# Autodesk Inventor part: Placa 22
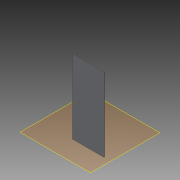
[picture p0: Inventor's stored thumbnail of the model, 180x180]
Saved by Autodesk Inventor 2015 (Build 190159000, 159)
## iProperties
Created: 2015-04
Part Number: Placa 22
Material: Generic
Document SubType Name: Modeling
Designer: suporte
Density: 1 g/cm^3
Appearance: Default
Author: suporte
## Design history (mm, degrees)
workplane "Work Plane1"
sketch "Sketch1"
  geometry: L1 (-87.5, -500)-(-87.5, -900) reference; L2 (-87.5, -400)-(812.5, -400); L3 (812.5, -400)-(812.5, -412.5); L4 (812.5, -412.5)-(-87.5, -412.5); L5 (-87.5, -412.5)-(-87.5, -400); 2 further points
  constraints: 8 end point, 2 parallel, 1 horizontal, 1 perpendicular
  dimensions: "d0" = 12.5 distance of L2.end L3.end
extrude "Extrusion1" new body sketch "Sketch1" distance "d1" = 2100; taper "d2" = 0 deg
body "Solid1"
node "Reference1"
node "Reference2"
